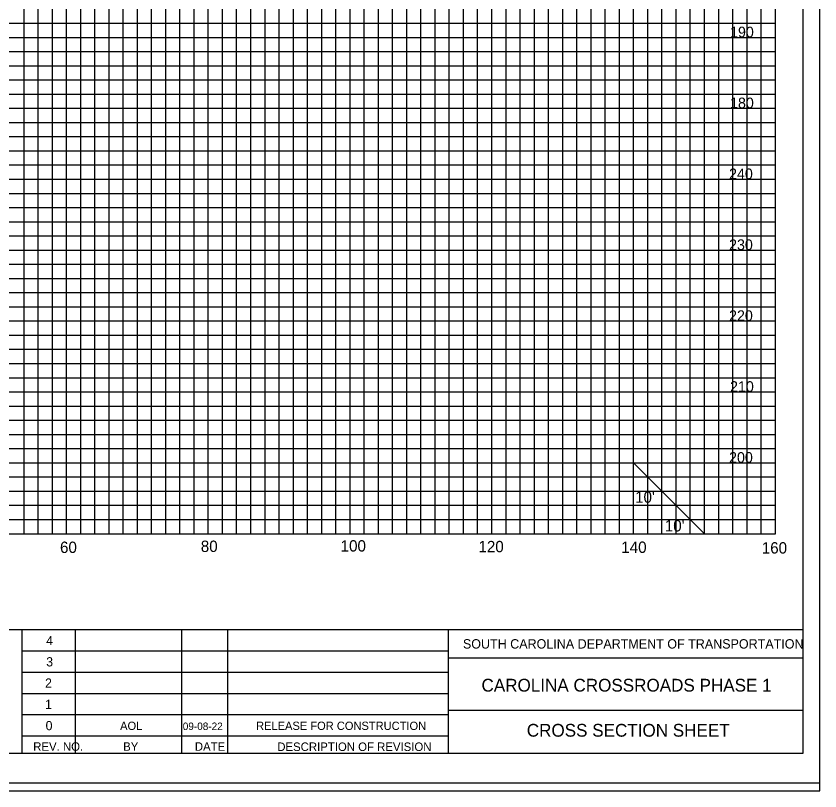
# Model space of a CAD drawing. Extents: x 967 to 1326, y 964 to 2584.
# Drawn here: x 1212.9 to 1326.3, y 1803.7 to 1913 of the extents above; entities that cross this region are included whole.
import ezdxf

# ---------------------------------------------------------------- set-up
doc = ezdxf.new("R2010")
doc.units = 0
for name, color, linetype in [('Default', 7, 'Continuous'), ('RD_GPK_XS_Cell', 7, 'Continuous'), ('RD_SHT_Misc1', 7, 'Continuous'), ('RD_XS_ExGround', 7, 'Continuous'), ('RD_XS_ExPaveRet', 7, 'Continuous'), ('RD_XS_Misc_Line', 7, 'Continuous'), ('RD_XS_TX_Elev_EX', 7, 'Continuous')]:
    doc.layers.add(name, color=color, linetype=linetype)

msp = doc.modelspace()

# ---------------------------------------------------------------- linework, layer by layer
at = {"layer": 'RD_GPK_XS_Cell'}
for p, q in [((1220, 1840), (1220, 2010)), ((1230, 1840), (1230, 2010)), ((1240, 1840), (1240, 2010)), ((1250, 1840), (1250, 2010)), ((1260, 1840), (1260, 2010)), ((1270, 1840), (1270, 2010)), ((1280, 1840), (1280, 2010)), ((1290, 1840), (1290, 2010)), ((1300, 1840), (1300, 2010)), ((1310, 1840), (1310, 2010)), ((1320, 1840), (1320, 2010)), ((1000, 1910), (1320, 1910)), ((1000, 1900), (1320, 1900)), ((1000, 1890), (1320, 1890)), ((1000, 1880), (1320, 1880)), ((1000, 1870), (1320, 1870)), ((1000, 1860), (1320, 1860)), ((1000, 1850), (1320, 1850)), ((1000, 1840), (1320, 1840))]:
    msp.add_line(p, q, dxfattribs=at)
at = {"layer": 'RD_XS_ExGround'}
for p, q in [((1214, 1840), (1214, 2010)), ((1216, 1840), (1216, 2010)), ((1218, 1840), (1218, 2010)), ((1222, 1840), (1222, 2010)), ((1224, 1840), (1224, 2010)), ((1226, 1840), (1226, 2010)), ((1228, 1840), (1228, 2010)), ((1232, 1840), (1232, 2010)), ((1234, 1840), (1234, 2010)), ((1236, 1840), (1236, 2010)), ((1238, 1840), (1238, 2010)), ((1242, 1840), (1242, 2010)), ((1244, 1840), (1244, 2010)), ((1246, 1840), (1246, 2010)), ((1248, 1840), (1248, 2010)), ((1252, 1840), (1252, 2010)), ((1254, 1840), (1254, 2010)), ((1256, 1840), (1256, 2010)), ((1258, 1840), (1258, 2010)), ((1262, 1840), (1262, 2010)), ((1264, 1840), (1264, 2010)), ((1266, 1840), (1266, 2010)), ((1268, 1840), (1268, 2010)), ((1272, 1840), (1272, 2010)), ((1274, 1840), (1274, 2010)), ((1276, 1840), (1276, 2010)), ((1278, 1840), (1278, 2010)), ((1282, 1840), (1282, 2010)), ((1284, 1840), (1284, 2010)), ((1286, 1840), (1286, 2010)), ((1288, 1840), (1288, 2010)), ((1292, 1840), (1292, 2010)), ((1294, 1840), (1294, 2010)), ((1296, 1840), (1296, 2010)), ((1298, 1840), (1298, 2010)), ((1302, 1840), (1302, 2010)), ((1304, 1840), (1304, 2010)), ((1306, 1840), (1306, 2010)), ((1308, 1840), (1308, 2010)), ((1312, 1840), (1312, 2010)), ((1314, 1840), (1314, 2010)), ((1316, 1840), (1316, 2010)), ((1318, 1840), (1318, 2010)), ((1000, 1912), (1320, 1912)), ((1000, 1908), (1320, 1908)), ((1000, 1906), (1320, 1906)), ((1000, 1904), (1320, 1904)), ((1000, 1902), (1320, 1902)), ((1000, 1898), (1320, 1898)), ((1000, 1896), (1320, 1896)), ((1000, 1894), (1320, 1894)), ((1000, 1892), (1320, 1892)), ((1000, 1888), (1320, 1888)), ((1000, 1886), (1320, 1886)), ((1000, 1884), (1320, 1884)), ((1000, 1882), (1320, 1882)), ((1000, 1878), (1320, 1878)), ((1000, 1876), (1320, 1876)), ((1000, 1874), (1320, 1874)), ((1000, 1872), (1320, 1872)), ((1000, 1868), (1320, 1868)), ((1000, 1866), (1320, 1866)), ((1000, 1864), (1320, 1864)), ((1000, 1862), (1320, 1862)), ((1000, 1858), (1320, 1858)), ((1000, 1856), (1320, 1856)), ((1000, 1854), (1320, 1854)), ((1000, 1852), (1320, 1852)), ((1000, 1848), (1320, 1848)), ((1000, 1846), (1320, 1846)), ((1000, 1844), (1320, 1844)), ((1000, 1842), (1320, 1842))]:
    msp.add_line(p, q, dxfattribs=at)
at = {"layer": 'RD_XS_ExPaveRet'}
for points in [[(967.41, 1803.72), (1326.28, 1803.72), (1326.28, 2023.72), (967.41, 2023.72)], [(988.52, 1804.84), (1326.28, 1804.84), (1326.28, 2022.6), (988.52, 2022.6)]]:
    msp.add_lwpolyline(points, close=True, dxfattribs=at)
at = {"layer": 'RD_XS_Misc_Line'}
msp.add_line((1300, 1850), (1310, 1840), dxfattribs=at)
at = {"layer": 'RD_XS_TX_Elev_EX'}
for p, q in [((1323.89, 2018.46), (1323.89, 1808.98)), ((996.11, 1826.49), (1323.89, 1826.49)), ((1213.76, 1808.94), (1213.76, 1826.49)), ((1221.26, 1808.95), (1221.26, 1826.48)), ((1236.26, 1808.95), (1236.26, 1826.48)), ((1242.76, 1808.95), (1242.76, 1826.48)), ((1273.88, 1808.98), (1273.88, 1826.49)), ((1213.76, 1823.48), (1273.88, 1823.48)), ((1323.93, 1822.43), (1273.88, 1822.43)), ((1213.76, 1820.48), (1273.88, 1820.48)), ((1213.76, 1817.48), (1273.88, 1817.48)), ((1213.76, 1814.48), (1273.88, 1814.48)), ((1323.89, 1815.04), (1273.88, 1815.04)), ((1213.76, 1811.48), (1273.88, 1811.48)), ((1323.89, 1808.98), (996.11, 1808.98))]:
    msp.add_line(p, q, dxfattribs=at)

# ---------------------------------------------------------------- texts
at = {"layer": 'Default'}
for s, p in [('190', (1313.61, 1910)), ('180', (1313.61, 1900)), ('240', (1313.47, 1890)), ('230', (1313.47, 1880)), ('220', (1313.47, 1870)), ('210', (1313.61, 1860)), ('200', (1313.47, 1850))]:
    msp.add_text(s, height=1.5, dxfattribs=at).set_placement(p)
at = {"layer": 'RD_SHT_Misc1'}
for s, height, p in [('AOL', 1.17, (1227.56, 1812.32)), ('09-08-22', 1.053, (1236.4, 1812.31)), ('RELEASE FOR CONSTRUCTION', 1.17, (1246.74, 1812.32))]:
    msp.add_text(s, height=height, dxfattribs=at).set_placement(p)
at = {"layer": 'RD_XS_Misc_Line'}
for s, height, p in [("10'", 1.6, (1300.21, 1844.36)), ("10'", 1.6, (1304.4, 1840.32)), ('60', 1.6, (1219.08, 1837.28)), ('80', 1.6, (1238.94, 1837.42)), ('100', 1.6, (1258.67, 1837.48)), ('120', 1.6, (1278.11, 1837.38)), ('140', 1.6, (1298.26, 1837.29)), ('160', 1.6, (1318.08, 1837.2)), ('4', 1.3, (1217.13, 1824.28)), ('SOUTH CAROLINA DEPARTMENT OF TRANSPORTATION', 1.32, (1275.92, 1823.8)), ('3', 1.3, (1217.13, 1821.28)), ('2', 1.3, (1216.97, 1818.28)), ('1', 1.3, (1216.97, 1815.28)), ('0', 1.3, (1217.05, 1812.28)), ('REV. NO.', 1.2, (1215.3, 1809.38)), ('BY', 1.2, (1227.99, 1809.38)), ('DATE', 1.2, (1238.1, 1809.38)), ('DESCRIPTION OF REVISION', 1.2, (1249.73, 1809.35))]:
    msp.add_text(s, height=height, dxfattribs=at).set_placement(p)
for s, p in [('CAROLINA CROSSROADS PHASE 1', (1278.54, 1817.73)), ('CROSS SECTION SHEET', (1284.93, 1811.37))]:
    msp.add_text(s, height=1.8, rotation=0, dxfattribs=at).set_placement(p)

doc.saveas('drawing.dxf')
